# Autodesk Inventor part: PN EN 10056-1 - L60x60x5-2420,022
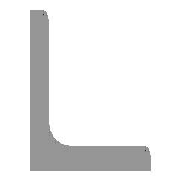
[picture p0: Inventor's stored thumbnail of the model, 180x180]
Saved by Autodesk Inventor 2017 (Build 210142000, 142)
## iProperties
Created: 2016-02
Part Number: PN EN 10056-1 - L60x60x5-2420,022
Material: Stal, miękka
Description: Kątownik równoramienny
Document SubType Name: Modeling
Standard: PN
Designer: X
Standards Organization: PN
Language: pl-PL
Size Designation: L60x60x5
Categories: <MemberInstance><Categories><Category DisplayName="Kształtowniki konstrukcyjne" InternalName="089c4875-fa83-4c05-b084-43b9cc11f5ed" Mnemonic="GRDR"><CategoryPar
Stock Number: L60x60x5
Density: 7.85 g/cm^3
Appearance: Częściowo polerowana
IsCustomPart: 1
_CCFamilyMember: 130
_CCFamilyDisplayName: PN EN 10056-1 (Kątownik równoramienny) - Kątownik równoramienny
_FrameMemberDoc: Frame Member File
_Version: 15.0.0
_GetPNFromCC: 1
Author: X
G_W: 60,000 mm
G_H: 60,000 mm
G_L: 2420,022 mm
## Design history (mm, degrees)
node "Płaszczyzna początkowa"
node "Płaszczyzna końcowa"
sketch "Szkic"
  geometry: L1 (-11.517, -3.517)-(-11.517, 39.483); L2 (-16.517, 43.483)-(-15.517, 43.483); L3 (-16.517, -16.517)-(-16.517, 43.483); L4 (-16.517, -16.517)-(43.483, -16.517); L5 (43.483, -15.517)-(43.483, -16.517); L6 (-3.517, -11.517)-(39.483, -11.517); L7 (0, 56.477)-(0, -28.683) reference; L8 (-28.683, 0)-(56.477, 0) reference; A1 r 8 centre (-3.517, -3.517) between (-11.517, -3.517) and (-3.517, -11.517); A2 r 4 centre (-15.517, 39.483) between (-11.517, 39.483) and (-15.517, 43.483); A3 r 4 centre (39.483, -15.517) between (43.483, -15.517) and (39.483, -11.517); 3 further points
  constraints: 12 end point, 6 point on circle, 6 point on line, 6 tangent, 3 centre point, 3 horizontal, 3 vertical, 1 equal radius
  dimensions: "d4" = 60 distance of L3.start L4.end (= b); "d6" = 60 distance of L3.start L2.start (= b); "d8" = 5 distance of point (43.483, -11.517) L4.end (= ParT); "d10" = 5 distance of L2.start point (-11.517, 43.483) (= ParT); "d17" = 8 radius of A1 (= R); "d18" = 4 radius of A2 (= R1); "d19" = 16.51748 distance between parallel lines of L8 L4 (= ex); "d20" = 16.51748 distance between parallel lines of L3 L7 (= d19)
extrude "Bryła" new body sketch "Szkic" stored distance "d11" = 2420.02174 (= G_L); taper "d12" = 0 deg
node "Driven Length"
  sketch "Sketch3"
    geometry: L1 (0, 0)-(10, 0) reference
    constraints: 2 end point, 1 horizontal
  workplane "Work Plane10"
  sketch "Sketch4"
    geometry: L1 (-2, -60)-(12, -60) reference; L2 (-2, 2360.022)-(12, 2360.022) reference
    dimensions: "d24" = 2420.02174 distance between parallel lines of L1 L2 (derived)
body "Solid1"
other parameters: "b" = 60 [user parameter; used in 3 equation terms], "ParT" = 5 [user parameter; used in 3 equation terms], "R" = 8 [user parameter; used in 1 equation term], "R1" = 4 [user parameter; used in 1 equation term], "G_L" = 2420.02174 (= d24) [user parameter; used in 1 equation term], "d7" = 4 (derived), "d9" = 4 (derived), "ex" = 16.51748 (computed from b, ParT) [user parameter; used in 1 equation term], "d22" = 2360.02174 (= G_OFFSET_END + B_L), "B_L" = 2300.02174 [user parameter; used in 1 equation term], "d23" = 90 deg
